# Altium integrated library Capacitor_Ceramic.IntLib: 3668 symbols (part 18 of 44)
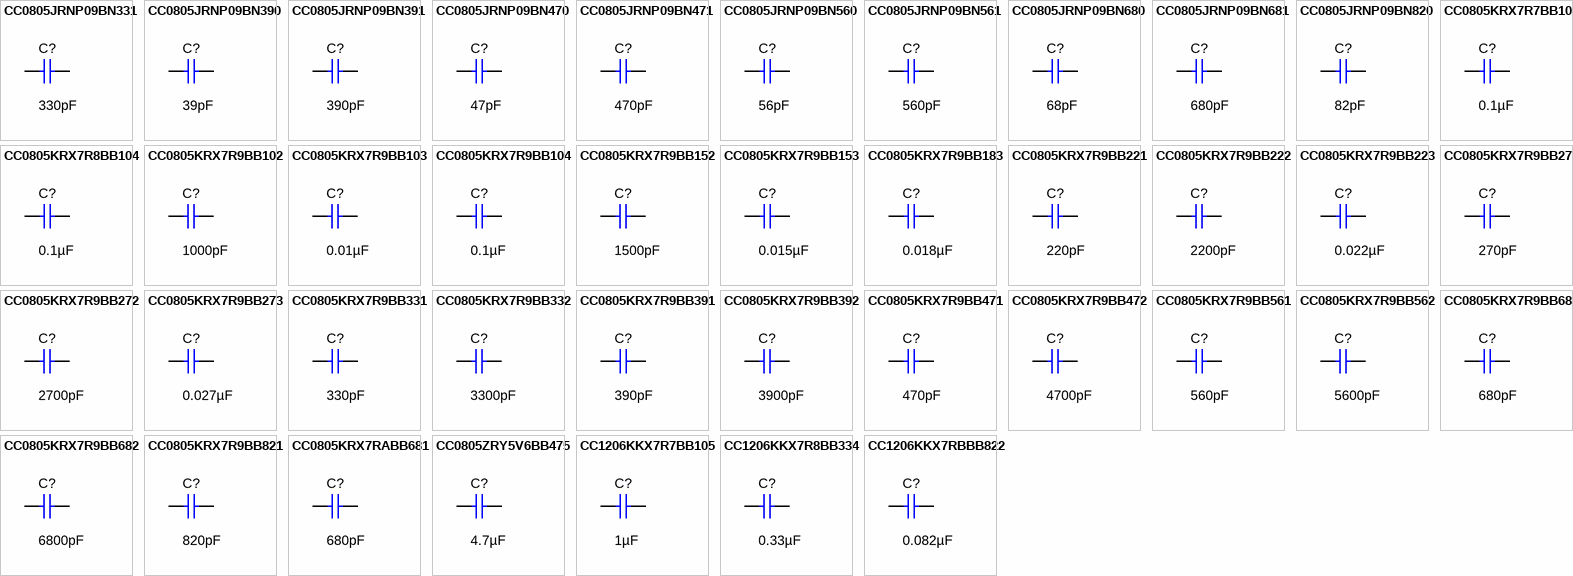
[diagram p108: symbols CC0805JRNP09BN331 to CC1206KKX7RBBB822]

## CC0805JRNP09BN820
designator C?  ValueDisplayed: 82pF  (hidden comment: CC0805JRNP09BN820)
CAP, CERM, 82 pF, 50 V,+/- 5%, C0G/NP0, 0805; Manufacturer: Yageo America; Polarized: N; CompType: Capacitor; Value: 82pF; U/M: EA; Cap_F: 0.000000000082; Tolerance_%: 5; VDC_V: 50; Value2: 50V; TaMin_C: -55; TaMax_C: 125; Cap_Case: 0805; SizeArea_mm2: 2.5; SizeAreaWB_mm2: 6.75; SizeX_mm: 2; SizeY_mm: 1.25; SizeZ_mm: 1.45; AEC Category: Q200
signal-integrity model Cap
simulation model Cap
footprint 0805_HV
footprint 0805_HV1
footprint 0805
footprint 0805M
footprint 0805L
pins: 1, 2

## CC0805KRX7R7BB104
designator C?  ValueDisplayed: 0.1µF  (hidden comment: CC0805KRX7R7BB104)
CAP, CERM, 0.1 µF, 16 V,+/- 10%, X7R, 0805; Manufacturer: Yageo America; Polarized: N; CompType: Capacitor; Value: 0.1uF; U/M: EA; Cap_F: 0.0000001; Tolerance_%: 10; VDC_V: 16; Value2: 16V; TaMin_C: -55; TaMax_C: 125; Cap_Case: 0805; SizeArea_mm2: 2.5; SizeAreaWB_mm2: 6.75; SizeX_mm: 2; SizeY_mm: 1.25; SizeZ_mm: 1.45; AEC Category: Q200; Green_Lifecycle: Active; Green_REACh: Passed
signal-integrity model Cap
simulation model Cap
footprint 0805_HV
footprint 0805_HV1
footprint 0805
footprint 0805M
footprint 0805L
pins: 1, 2

## CC0805KRX7R8BB104
designator C?  ValueDisplayed: 0.1µF  (hidden comment: CC0805KRX7R8BB104)
CAP, CERM, 0.1 µF, 25 V,+/- 10%, X7R, 0805; Manufacturer: Yageo America; Polarized: N; CompType: Capacitor; Value: 0.1uF; U/M: EA; Cap_F: 0.0000001; Tolerance_%: 10; VDC_V: 25; Value2: 25V; TaMin_C: -55; TaMax_C: 125; Cap_Case: 0805; SizeArea_mm2: 2.5; SizeAreaWB_mm2: 6.75; SizeX_mm: 2; SizeY_mm: 1.25; SizeZ_mm: 1.45; AEC Category: Q200; Green_Lifecycle: Active; Green_REACh: Passed
signal-integrity model Cap
simulation model Cap
footprint 0805_HV
footprint 0805_HV1
footprint 0805
footprint 0805M
footprint 0805L
pins: 1, 2

## CC0805KRX7R9BB102
designator C?  ValueDisplayed: 1000pF  (hidden comment: CC0805KRX7R9BB102)
CAP, CERM, 1000 pF, 50 V,+/- 10%, X7R, 0805; Manufacturer: Yageo America; Polarized: N; CompType: Capacitor; Value: 1000pF; U/M: EA; Cap_F: 0.000000001; Tolerance_%: 10; VDC_V: 50; Value2: 50V; TaMin_C: -55; TaMax_C: 125; Cap_Case: 0805; SizeArea_mm2: 2.5; SizeAreaWB_mm2: 6.75; SizeX_mm: 2; SizeY_mm: 1.25; SizeZ_mm: 1.45; AEC Category: Q200
signal-integrity model Cap
simulation model Cap
footprint 0805_HV
footprint 0805_HV1
footprint 0805
footprint 0805M
footprint 0805L
pins: 1, 2

## CC0805KRX7R9BB103
designator C?  ValueDisplayed: 0.01µF  (hidden comment: CC0805KRX7R9BB103)
CAP, CERM, 0.01 µF, 50 V,+/- 10%, X7R, 0805; Manufacturer: Yageo America; Polarized: N; CompType: Capacitor; Value: 0.01uF; U/M: EA; Cap_F: 0.00000001; Tolerance_%: 10; VDC_V: 50; Value2: 50V; TaMin_C: -55; TaMax_C: 125; Cap_Case: 0805; SizeArea_mm2: 2.5; SizeAreaWB_mm2: 6.75; SizeX_mm: 2; SizeY_mm: 1.25; SizeZ_mm: 1.45; AEC Category: Q200; Green_Lifecycle: Active; Green_REACh: Passed
signal-integrity model Cap
simulation model Cap
footprint 0805_HV
footprint 0805_HV1
footprint 0805
footprint 0805M
footprint 0805L
pins: 1, 2

## CC0805KRX7R9BB104
designator C?  ValueDisplayed: 0.1µF  (hidden comment: CC0805KRX7R9BB104)
CAP, CERM, 0.1 µF, 50 V,+/- 10%, X7R, 0805; Manufacturer: Yageo America; Polarized: N; CompType: Capacitor; Value: 0.1uF; U/M: EA; Cap_F: 0.0000001; Tolerance_%: 10; VDC_V: 50; Value2: 50V; TaMin_C: -55; TaMax_C: 125; Cap_Case: 0805; SizeArea_mm2: 2.5; SizeAreaWB_mm2: 6.75; SizeX_mm: 2; SizeY_mm: 1.25; SizeZ_mm: 1.45; AEC Category: Q200; Green_Lifecycle: Active; Green_REACh: Passed
signal-integrity model Cap
simulation model Cap
footprint 0805_HV
footprint 0805_HV1
footprint 0805
footprint 0805M
footprint 0805L
pins: 1, 2

## CC0805KRX7R9BB152
designator C?  ValueDisplayed: 1500pF  (hidden comment: CC0805KRX7R9BB152)
CAP, CERM, 1500 pF, 50 V,+/- 10%, X7R, 0805; Manufacturer: Yageo America; Polarized: N; CompType: Capacitor; Value: 1500pF; U/M: EA; Cap_F: 0.0000000015; Tolerance_%: 10; VDC_V: 50; Value2: 50V; TaMin_C: -55; TaMax_C: 125; Cap_Case: 0805; SizeArea_mm2: 2.5; SizeAreaWB_mm2: 6.75; SizeX_mm: 2; SizeY_mm: 1.25; SizeZ_mm: 1.45; AEC Category: Q200
signal-integrity model Cap
simulation model Cap
footprint 0805_HV
footprint 0805_HV1
footprint 0805
footprint 0805M
footprint 0805L
pins: 1, 2

## CC0805KRX7R9BB153
designator C?  ValueDisplayed: 0.015µF  (hidden comment: CC0805KRX7R9BB153)
CAP, CERM, 0.015 µF, 50 V,+/- 10%, X7R, 0805; Manufacturer: Yageo America; Polarized: N; CompType: Capacitor; Value: 0.015uF; U/M: EA; Cap_F: 0.000000015; Tolerance_%: 10; VDC_V: 50; Value2: 50V; TaMin_C: -55; TaMax_C: 125; Cap_Case: 0805; SizeArea_mm2: 2.5; SizeAreaWB_mm2: 6.75; SizeX_mm: 2; SizeY_mm: 1.25; SizeZ_mm: 1.45; AEC Category: Q200
signal-integrity model Cap
simulation model Cap
footprint 0805_HV
footprint 0805_HV1
footprint 0805
footprint 0805M
footprint 0805L
pins: 1, 2

## CC0805KRX7R9BB183
designator C?  ValueDisplayed: 0.018µF  (hidden comment: CC0805KRX7R9BB183)
CAP, CERM, 0.018 µF, 50 V,+/- 10%, X7R, 0805; Manufacturer: Yageo America; Polarized: N; CompType: Capacitor; Value: 0.018uF; U/M: EA; Cap_F: 0.000000018; Tolerance_%: 10; VDC_V: 50; Value2: 50V; TaMin_C: -55; TaMax_C: 125; Cap_Case: 0805; SizeArea_mm2: 2.5; SizeAreaWB_mm2: 6.75; SizeX_mm: 2; SizeY_mm: 1.25; SizeZ_mm: 1.45; AEC Category: Q200
signal-integrity model Cap
simulation model Cap
footprint 0805_HV
footprint 0805_HV1
footprint 0805
footprint 0805M
footprint 0805L
pins: 1, 2

## CC0805KRX7R9BB221
designator C?  ValueDisplayed: 220pF  (hidden comment: CC0805KRX7R9BB221)
CAP, CERM, 220 pF, 50 V,+/- 10%, X7R, 0805; Manufacturer: Yageo America; Polarized: N; CompType: Capacitor; Value: 220pF; U/M: EA; Cap_F: 0.00000000022; Tolerance_%: 10; VDC_V: 50; Value2: 50V; TaMin_C: -55; TaMax_C: 125; Cap_Case: 0805; SizeArea_mm2: 2.5; SizeAreaWB_mm2: 6.75; SizeX_mm: 2; SizeY_mm: 1.25; SizeZ_mm: 1.45; AEC Category: Q200
signal-integrity model Cap
simulation model Cap
footprint 0805_HV
footprint 0805_HV1
footprint 0805
footprint 0805M
footprint 0805L
pins: 1, 2

## CC0805KRX7R9BB222
designator C?  ValueDisplayed: 2200pF  (hidden comment: CC0805KRX7R9BB222)
CAP, CERM, 2200 pF, 50 V,+/- 10%, X7R, 0805; Manufacturer: Yageo America; Polarized: N; CompType: Capacitor; Value: 2200pF; U/M: EA; Cap_F: 0.0000000022; Tolerance_%: 10; VDC_V: 50; Value2: 50V; TaMin_C: -55; TaMax_C: 125; Cap_Case: 0805; SizeArea_mm2: 2.5; SizeAreaWB_mm2: 6.75; SizeX_mm: 2; SizeY_mm: 1.25; SizeZ_mm: 1.45; AEC Category: Q200
signal-integrity model Cap
simulation model Cap
footprint 0805_HV
footprint 0805_HV1
footprint 0805
footprint 0805M
footprint 0805L
pins: 1, 2

## CC0805KRX7R9BB223
designator C?  ValueDisplayed: 0.022µF  (hidden comment: CC0805KRX7R9BB223)
CAP, CERM, 0.022 µF, 50 V,+/- 10%, X7R, 0805; Manufacturer: Yageo America; Polarized: N; CompType: Capacitor; Value: 0.022uF; U/M: EA; Cap_F: 0.000000022; Tolerance_%: 10; VDC_V: 50; Value2: 50V; TaMin_C: -55; TaMax_C: 125; Cap_Case: 0805; SizeArea_mm2: 2.5; SizeAreaWB_mm2: 6.75; SizeX_mm: 2; SizeY_mm: 1.25; SizeZ_mm: 1.45; AEC Category: Q200
signal-integrity model Cap
simulation model Cap
footprint 0805_HV
footprint 0805_HV1
footprint 0805
footprint 0805M
footprint 0805L
pins: 1, 2

## CC0805KRX7R9BB271
designator C?  ValueDisplayed: 270pF  (hidden comment: CC0805KRX7R9BB271)
CAP, CERM, 270 pF, 50 V,+/- 10%, X7R, 0805; Manufacturer: Yageo America; Polarized: N; CompType: Capacitor; Value: 270pF; U/M: EA; Cap_F: 0.00000000027; Tolerance_%: 10; VDC_V: 50; Value2: 50V; TaMin_C: -55; TaMax_C: 125; Cap_Case: 0805; SizeArea_mm2: 2.5; SizeAreaWB_mm2: 6.75; SizeX_mm: 2; SizeY_mm: 1.25; SizeZ_mm: 1.45; AEC Category: Q200
signal-integrity model Cap
simulation model Cap
footprint 0805_HV
footprint 0805_HV1
footprint 0805
footprint 0805M
footprint 0805L
pins: 1, 2

## CC0805KRX7R9BB272
designator C?  ValueDisplayed: 2700pF  (hidden comment: CC0805KRX7R9BB272)
CAP, CERM, 2700 pF, 50 V,+/- 10%, X7R, 0805; Manufacturer: Yageo America; Polarized: N; CompType: Capacitor; Value: 2700pF; U/M: EA; Cap_F: 0.0000000027; Tolerance_%: 10; VDC_V: 50; Value2: 50V; TaMin_C: -55; TaMax_C: 125; Cap_Case: 0805; SizeArea_mm2: 2.5; SizeAreaWB_mm2: 6.75; SizeX_mm: 2; SizeY_mm: 1.25; SizeZ_mm: 1.45; AEC Category: Q200
signal-integrity model Cap
simulation model Cap
footprint 0805_HV
footprint 0805_HV1
footprint 0805
footprint 0805M
footprint 0805L
pins: 1, 2

## CC0805KRX7R9BB273
designator C?  ValueDisplayed: 0.027µF  (hidden comment: CC0805KRX7R9BB273)
CAP, CERM, 0.027 µF, 50 V,+/- 10%, X7R, 0805; Manufacturer: Yageo America; Polarized: N; CompType: Capacitor; Value: 0.027uF; U/M: EA; Cap_F: 0.000000027; Tolerance_%: 10; VDC_V: 50; Value2: 50V; TaMin_C: -55; TaMax_C: 125; Cap_Case: 0805; SizeArea_mm2: 2.5; SizeAreaWB_mm2: 6.75; SizeX_mm: 2; SizeY_mm: 1.25; SizeZ_mm: 1.45; AEC Category: Q200
signal-integrity model Cap
simulation model Cap
footprint 0805_HV
footprint 0805_HV1
footprint 0805
footprint 0805M
footprint 0805L
pins: 1, 2

## CC0805KRX7R9BB331
designator C?  ValueDisplayed: 330pF  (hidden comment: CC0805KRX7R9BB331)
CAP, CERM, 330 pF, 50 V,+/- 10%, X7R, 0805; Manufacturer: Yageo America; Polarized: N; CompType: Capacitor; Value: 330pF; U/M: EA; Cap_F: 0.00000000033; Tolerance_%: 10; VDC_V: 50; Value2: 50V; TaMin_C: -55; TaMax_C: 125; Cap_Case: 0805; SizeArea_mm2: 2.5; SizeAreaWB_mm2: 6.75; SizeX_mm: 2; SizeY_mm: 1.25; SizeZ_mm: 1.45; AEC Category: Q200
signal-integrity model Cap
simulation model Cap
footprint 0805_HV
footprint 0805_HV1
footprint 0805
footprint 0805M
footprint 0805L
pins: 1, 2

## CC0805KRX7R9BB332
designator C?  ValueDisplayed: 3300pF  (hidden comment: CC0805KRX7R9BB332)
CAP, CERM, 3300 pF, 50 V,+/- 10%, X7R, 0805; Manufacturer: Yageo America; Polarized: N; CompType: Capacitor; Value: 3300pF; U/M: EA; Cap_F: 0.0000000033; Tolerance_%: 10; VDC_V: 50; Value2: 50V; TaMin_C: -55; TaMax_C: 125; Cap_Case: 0805; SizeArea_mm2: 2.5; SizeAreaWB_mm2: 6.75; SizeX_mm: 2; SizeY_mm: 1.25; SizeZ_mm: 1.45; AEC Category: Q200
signal-integrity model Cap
simulation model Cap
footprint 0805_HV
footprint 0805_HV1
footprint 0805
footprint 0805M
footprint 0805L
pins: 1, 2

## CC0805KRX7R9BB391
designator C?  ValueDisplayed: 390pF  (hidden comment: CC0805KRX7R9BB391)
CAP, CERM, 390 pF, 50 V,+/- 10%, X7R, 0805; Manufacturer: Yageo America; Polarized: N; CompType: Capacitor; Value: 390pF; U/M: EA; Cap_F: 0.00000000039; Tolerance_%: 10; VDC_V: 50; Value2: 50V; TaMin_C: -55; TaMax_C: 125; Cap_Case: 0805; SizeArea_mm2: 2.5; SizeAreaWB_mm2: 6.75; SizeX_mm: 2; SizeY_mm: 1.25; SizeZ_mm: 1.45; AEC Category: Q200
signal-integrity model Cap
simulation model Cap
footprint 0805_HV
footprint 0805_HV1
footprint 0805
footprint 0805M
footprint 0805L
pins: 1, 2

## CC0805KRX7R9BB392
designator C?  ValueDisplayed: 3900pF  (hidden comment: CC0805KRX7R9BB392)
CAP, CERM, 3900 pF, 50 V,+/- 10%, X7R, 0805; Manufacturer: Yageo America; Polarized: N; CompType: Capacitor; Value: 3900pF; U/M: EA; Cap_F: 0.0000000039; Tolerance_%: 10; VDC_V: 50; Value2: 50V; TaMin_C: -55; TaMax_C: 125; Cap_Case: 0805; SizeArea_mm2: 2.5; SizeAreaWB_mm2: 6.75; SizeX_mm: 2; SizeY_mm: 1.25; SizeZ_mm: 1.45; AEC Category: Q200
signal-integrity model Cap
simulation model Cap
footprint 0805_HV
footprint 0805_HV1
footprint 0805
footprint 0805M
footprint 0805L
pins: 1, 2

## CC0805KRX7R9BB471
designator C?  ValueDisplayed: 470pF  (hidden comment: CC0805KRX7R9BB471)
CAP, CERM, 470 pF, 50 V,+/- 10%, X7R, 0805; Manufacturer: Yageo America; Polarized: N; CompType: Capacitor; Value: 470pF; U/M: EA; Cap_F: 0.00000000047; Tolerance_%: 10; VDC_V: 50; Value2: 50V; TaMin_C: -55; TaMax_C: 125; Cap_Case: 0805; SizeArea_mm2: 2.5; SizeAreaWB_mm2: 6.75; SizeX_mm: 2; SizeY_mm: 1.25; SizeZ_mm: 1.45; AEC Category: Q200; Green_Lifecycle: Active; Green_REACh: Passed
signal-integrity model Cap
simulation model Cap
footprint 0805_HV
footprint 0805_HV1
footprint 0805
footprint 0805M
footprint 0805L
pins: 1, 2

## CC0805KRX7R9BB472
designator C?  ValueDisplayed: 4700pF  (hidden comment: CC0805KRX7R9BB472)
CAP, CERM, 4700 pF, 50 V,+/- 10%, X7R, 0805; Manufacturer: Yageo America; Polarized: N; CompType: Capacitor; Value: 4700pF; U/M: EA; Cap_F: 0.0000000047; Tolerance_%: 10; VDC_V: 50; Value2: 50V; TaMin_C: -55; TaMax_C: 125; Cap_Case: 0805; SizeArea_mm2: 2.5; SizeAreaWB_mm2: 6.75; SizeX_mm: 2; SizeY_mm: 1.25; SizeZ_mm: 1.45; AEC Category: Q200
signal-integrity model Cap
simulation model Cap
footprint 0805_HV
footprint 0805_HV1
footprint 0805
footprint 0805M
footprint 0805L
pins: 1, 2

## CC0805KRX7R9BB561
designator C?  ValueDisplayed: 560pF  (hidden comment: CC0805KRX7R9BB561)
CAP, CERM, 560 pF, 50 V,+/- 10%, X7R, 0805; Manufacturer: Yageo America; Polarized: N; CompType: Capacitor; Value: 560pF; U/M: EA; Cap_F: 0.00000000056; Tolerance_%: 10; VDC_V: 50; Value2: 50V; TaMin_C: -55; TaMax_C: 125; Cap_Case: 0805; SizeArea_mm2: 2.5; SizeAreaWB_mm2: 6.75; SizeX_mm: 2; SizeY_mm: 1.25; SizeZ_mm: 1.45; AEC Category: Q200
signal-integrity model Cap
simulation model Cap
footprint 0805_HV
footprint 0805_HV1
footprint 0805
footprint 0805M
footprint 0805L
pins: 1, 2

## CC0805KRX7R9BB562
designator C?  ValueDisplayed: 5600pF  (hidden comment: CC0805KRX7R9BB562)
CAP, CERM, 5600 pF, 50 V,+/- 10%, X7R, 0805; Manufacturer: Yageo America; Polarized: N; CompType: Capacitor; Value: 5600pF; U/M: EA; Cap_F: 0.0000000056; Tolerance_%: 10; VDC_V: 50; Value2: 50V; TaMin_C: -55; TaMax_C: 125; Cap_Case: 0805; SizeArea_mm2: 2.5; SizeAreaWB_mm2: 6.75; SizeX_mm: 2; SizeY_mm: 1.25; SizeZ_mm: 1.45; AEC Category: Q200
signal-integrity model Cap
simulation model Cap
footprint 0805_HV
footprint 0805_HV1
footprint 0805
footprint 0805M
footprint 0805L
pins: 1, 2

## CC0805KRX7R9BB681
designator C?  ValueDisplayed: 680pF  (hidden comment: CC0805KRX7R9BB681)
CAP, CERM, 680 pF, 50 V,+/- 10%, X7R, 0805; Manufacturer: Yageo America; Polarized: N; CompType: Capacitor; Value: 680pF; U/M: EA; Cap_F: 0.00000000068; Tolerance_%: 10; VDC_V: 50; Value2: 50V; TaMin_C: -55; TaMax_C: 125; Cap_Case: 0805; SizeArea_mm2: 2.5; SizeAreaWB_mm2: 6.75; SizeX_mm: 2; SizeY_mm: 1.25; SizeZ_mm: 1.45; AEC Category: Q200
signal-integrity model Cap
simulation model Cap
footprint 0805_HV
footprint 0805_HV1
footprint 0805
footprint 0805M
footprint 0805L
pins: 1, 2

## CC0805KRX7R9BB682
designator C?  ValueDisplayed: 6800pF  (hidden comment: CC0805KRX7R9BB682)
CAP, CERM, 6800 pF, 50 V,+/- 10%, X7R, 0805; Manufacturer: Yageo America; Polarized: N; CompType: Capacitor; Value: 6800pF; U/M: EA; Cap_F: 0.0000000068; Tolerance_%: 10; VDC_V: 50; Value2: 50V; TaMin_C: -55; TaMax_C: 125; Cap_Case: 0805; SizeArea_mm2: 2.5; SizeAreaWB_mm2: 6.75; SizeX_mm: 2; SizeY_mm: 1.25; SizeZ_mm: 1.45; AEC Category: Q200
signal-integrity model Cap
simulation model Cap
footprint 0805_HV
footprint 0805_HV1
footprint 0805
footprint 0805M
footprint 0805L
pins: 1, 2

## CC0805KRX7R9BB821
designator C?  ValueDisplayed: 820pF  (hidden comment: CC0805KRX7R9BB821)
CAP, CERM, 820 pF, 50 V,+/- 10%, X7R, 0805; Manufacturer: Yageo America; Polarized: N; CompType: Capacitor; Value: 820pF; U/M: EA; Cap_F: 0.00000000082; Tolerance_%: 10; VDC_V: 50; Value2: 50V; TaMin_C: -55; TaMax_C: 125; Cap_Case: 0805; SizeArea_mm2: 2.5; SizeAreaWB_mm2: 6.75; SizeX_mm: 2; SizeY_mm: 1.25; SizeZ_mm: 1.45; AEC Category: Q200
signal-integrity model Cap
simulation model Cap
footprint 0805_HV
footprint 0805_HV1
footprint 0805
footprint 0805M
footprint 0805L
pins: 1, 2

## CC0805KRX7RABB681
designator C?  ValueDisplayed: 680pF  (hidden comment: CC0805KRX7RABB681)
CAP, CERM, 680 pF, 200 V,+/- 10%, X7R, 0805; Manufacturer: Yageo America; Polarized: N; CompType: Capacitor; Value: 680pF; U/M: EA; Cap_F: 0.00000000068; Tolerance_%: 10; VDC_V: 200; Value2: 200V; TaMin_C: -55; TaMax_C: 125; Cap_Case: 0805; SizeArea_mm2: 2.5; SizeAreaWB_mm2: 6.75; SizeX_mm: 2; SizeY_mm: 1.25; SizeZ_mm: 1.45; AEC Category: Q200; Green_Lifecycle: Active; Green_REACh: Passed
signal-integrity model Cap
simulation model Cap
footprint 0805_HV
footprint 0805_HV1
footprint 0805
footprint 0805M
footprint 0805L
pins: 1, 2

## CC0805ZRY5V6BB475
designator C?  ValueDisplayed: 4.7µF  (hidden comment: CC0805ZRY5V6BB475)
CAP, CERM, 4.7 µF, 10 V,+80/-20%, Y5V, 0805; Manufacturer: Yageo America; Polarized: N; CompType: Capacitor; Value: 4.7uF; U/M: EA; Cap_F: 0.0000047; Tolerance_%: 80; VDC_V: 10; Value2: 10V; TaMin_C: -30; TaMax_C: 85; Cap_Case: 0805; SizeArea_mm2: 2.5; SizeAreaWB_mm2: 6.75; SizeX_mm: 2; SizeY_mm: 1.25; SizeZ_mm: 1.45; AEC Category: Q200
signal-integrity model Cap
simulation model Cap
footprint 0805_HV
footprint 0805_HV1
footprint 0805
footprint 0805M
footprint 0805L
pins: 1, 2

## CC1206KKX7R7BB105
designator C?  ValueDisplayed: 1µF  (hidden comment: CC1206KKX7R7BB105)
CAP, CERM, 1 µF, 16 V,+/- 10%, X7R, 1206; Manufacturer: Yageo America; Polarized: N; CompType: Capacitor; Value: 1uF; U/M: EA; Cap_F: 0.000001; Tolerance_%: 10; VDC_V: 16; Value2: 16V; TaMin_C: -55; TaMax_C: 125; Cap_Case: 1206; SizeArea_mm2: 5.12; SizeAreaWB_mm2: 10.92; SizeX_mm: 3.2; SizeY_mm: 1.6; SizeZ_mm: 1.35; AEC Category: Q200; Green_Lifecycle: Active; Green_REACh: Passed
signal-integrity model Cap
simulation model Cap
footprint 1206
footprint 1206M
footprint 1206L
pins: 1, 2

## CC1206KKX7R8BB334
designator C?  ValueDisplayed: 0.33µF  (hidden comment: CC1206KKX7R8BB334)
CAP, CERM, 0.33 µF, 25 V,+/- 10%, X7R, 1206; Manufacturer: Yageo America; Polarized: N; CompType: Capacitor; Value: 0.33uF; U/M: EA; Cap_F: 0.00000033; Tolerance_%: 10; VDC_V: 25; Value2: 25V; TaMin_C: -55; TaMax_C: 125; Cap_Case: 1206; SizeArea_mm2: 5.12; SizeAreaWB_mm2: 10.92; SizeX_mm: 3.2; SizeY_mm: 1.6; SizeZ_mm: 1.35; AEC Category: Q200
signal-integrity model Cap
simulation model Cap
footprint 1206
footprint 1206M
footprint 1206L
pins: 1, 2

## CC1206KKX7RBBB822
designator C?  ValueDisplayed: 0.082µF  (hidden comment: CC1206KKX7RBBB822)
CAP, CERM, 0.082 µF, 500 V,+/- 10%, X7R, 1206; Manufacturer: Yageo America; Polarized: N; CompType: Capacitor; Value: 0.082uF; U/M: EA; Cap_F: 0.000000082; Tolerance_%: 10; VDC_V: 500; Value2: 500V; TaMin_C: -55; TaMax_C: 125; Cap_Case: 1206; SizeArea_mm2: 5.12; SizeAreaWB_mm2: 10.92; SizeX_mm: 3.2; SizeY_mm: 1.6; SizeZ_mm: 1.35; AEC Category: Q200
signal-integrity model Cap
simulation model Cap
footprint 1206
footprint 1206M
footprint 1206L
pins: 1, 2

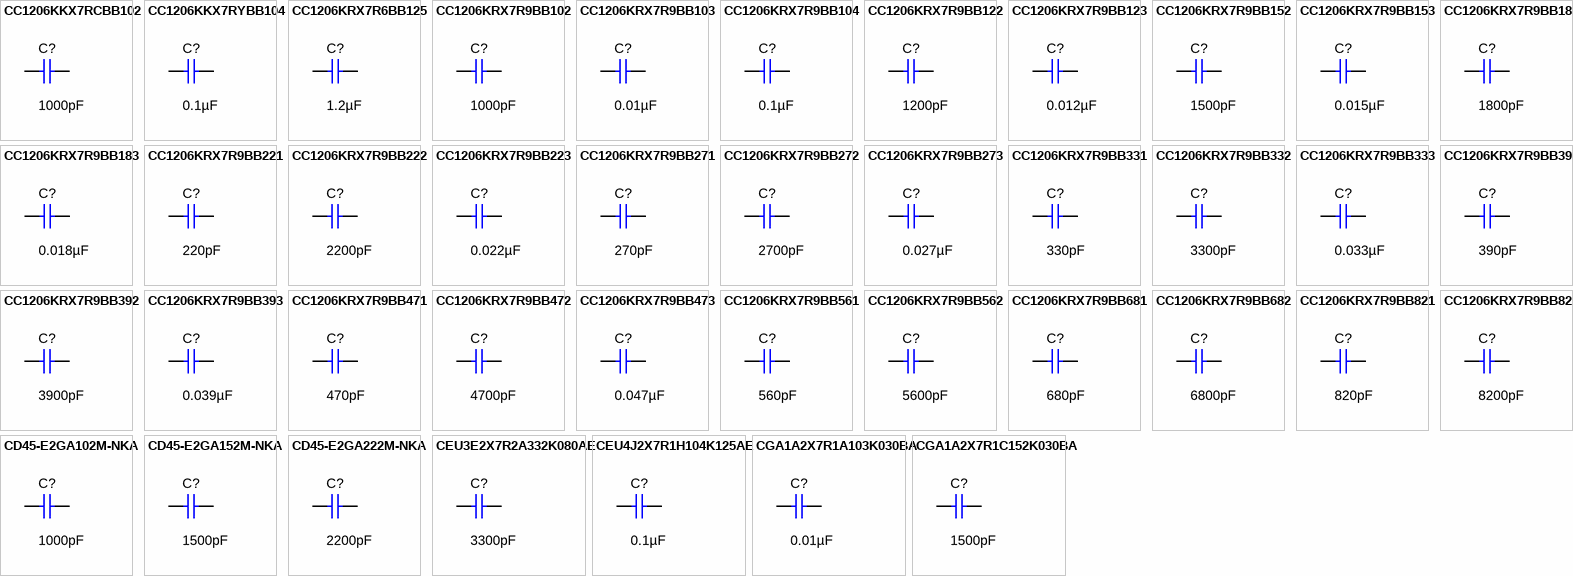
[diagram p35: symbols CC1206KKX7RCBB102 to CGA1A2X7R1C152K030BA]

## CC1206KKX7RCBB102
designator C?  ValueDisplayed: 1000pF  (hidden comment: CC1206KKX7RCBB102)
CAP, CERM, 1000 pF, 1000 V,+/- 10%, X7R, 1206; Manufacturer: Yageo America; Polarized: N; CompType: Capacitor; Value: 1000pF; U/M: EA; Cap_F: 0.000000001; Tolerance_%: 10; VDC_V: 1000; Value2: 1000V; TaMin_C: -55; TaMax_C: 125; Cap_Case: 1206; SizeArea_mm2: 5.12; SizeAreaWB_mm2: 10.92; SizeX_mm: 3.2; SizeY_mm: 1.6; SizeZ_mm: 1.35; AEC Category: Q200; Green_Lifecycle: Active; Green_REACh: Passed
signal-integrity model Cap
simulation model Cap
footprint 1206
footprint 1206M
footprint 1206L
pins: 1, 2

## CC1206KKX7RYBB104
designator C?  ValueDisplayed: 0.1µF  (hidden comment: CC1206KKX7RYBB104)
CAP, CERM, 0.1 µF, 250 V,+/- 10%, X7R, 1206; Manufacturer: Yageo America; Polarized: N; CompType: Capacitor; Value: 0.1uF; U/M: EA; Cap_F: 0.0000001; Tolerance_%: 10; VDC_V: 250; Value2: 250V; TaMin_C: -55; TaMax_C: 125; Cap_Case: 1206; SizeArea_mm2: 5.12; SizeAreaWB_mm2: 10.92; SizeX_mm: 3.2; SizeY_mm: 1.6; SizeZ_mm: 1.35; AEC Category: Q200
signal-integrity model Cap
simulation model Cap
footprint 1206
footprint 1206M
footprint 1206L
pins: 1, 2

## CC1206KRX7R6BB125
designator C?  ValueDisplayed: 1.2µF  (hidden comment: CC1206KRX7R6BB125)
CAP, CERM, 1.2 µF, 10 V,+/- 10%, X7R, 1206; Manufacturer: Yageo America; Polarized: N; CompType: Capacitor; Value: 1.2uF; U/M: EA; Cap_F: 0.0000012; Tolerance_%: 10; Value2: 10V; TaMin_C: -55; TaMax_C: 125; Cap_Case: 1206; SizeArea_mm2: 5.12; SizeAreaWB_mm2: 10.92; SizeX_mm: 3.2; SizeY_mm: 1.6; SizeZ_mm: 1.35; AEC Category: Q200
signal-integrity model Cap
simulation model Cap
footprint 1206
footprint 1206M
footprint 1206L
pins: 1, 2

## CC1206KRX7R9BB102
designator C?  ValueDisplayed: 1000pF  (hidden comment: CC1206KRX7R9BB102)
CAP, CERM, 1000 pF, 50 V,+/- 10%, X7R, 1206; Manufacturer: Yageo America; Polarized: N; CompType: Capacitor; Value: 1000pF; U/M: EA; Cap_F: 0.000000001; Tolerance_%: 10; VDC_V: 50; Value2: 50V; TaMin_C: -55; TaMax_C: 125; Cap_Case: 1206; SizeArea_mm2: 5.12; SizeAreaWB_mm2: 10.92; SizeX_mm: 3.2; SizeY_mm: 1.6; SizeZ_mm: 1.35; AEC Category: Q200
signal-integrity model Cap
simulation model Cap
footprint 1206
footprint 1206M
footprint 1206L
pins: 1, 2

## CC1206KRX7R9BB103
designator C?  ValueDisplayed: 0.01µF  (hidden comment: CC1206KRX7R9BB103)
CAP, CERM, 0.01 µF, 50 V,+/- 10%, X7R, 1206; Manufacturer: Yageo America; Polarized: N; CompType: Capacitor; Value: 0.01uF; U/M: EA; Cap_F: 0.00000001; Tolerance_%: 10; VDC_V: 50; Value2: 50V; TaMin_C: -55; TaMax_C: 125; Cap_Case: 1206; SizeArea_mm2: 5.12; SizeAreaWB_mm2: 10.92; SizeX_mm: 3.2; SizeY_mm: 1.6; SizeZ_mm: 1.35; AEC Category: Q200; Green_Lifecycle: Active; Green_REACh: Passed
signal-integrity model Cap
simulation model Cap
footprint 1206
footprint 1206M
footprint 1206L
pins: 1, 2

## CC1206KRX7R9BB104
designator C?  ValueDisplayed: 0.1µF  (hidden comment: CC1206KRX7R9BB104)
CAP, CERM, 0.1 µF, 50 V,+/- 10%, X7R, 1206; Manufacturer: Yageo America; Polarized: N; CompType: Capacitor; Value: 0.1uF; U/M: EA; Cap_F: 0.0000001; Tolerance_%: 10; VDC_V: 50; Value2: 50V; TaMin_C: -55; TaMax_C: 125; Cap_Case: 1206; SizeArea_mm2: 5.12; SizeAreaWB_mm2: 10.92; SizeX_mm: 3.2; SizeY_mm: 1.6; SizeZ_mm: 1.35; AEC Category: Q200
signal-integrity model Cap
simulation model Cap
footprint 1206
footprint 1206M
footprint 1206L
pins: 1, 2

## CC1206KRX7R9BB122
designator C?  ValueDisplayed: 1200pF  (hidden comment: CC1206KRX7R9BB122)
CAP, CERM, 1200 pF, 50 V,+/- 10%, X7R, 1206; Manufacturer: Yageo America; Polarized: N; CompType: Capacitor; Value: 1200pF; U/M: EA; Cap_F: 0.0000000012; Tolerance_%: 10; VDC_V: 50; Value2: 50V; TaMin_C: -55; TaMax_C: 125; Cap_Case: 1206; SizeArea_mm2: 5.12; SizeAreaWB_mm2: 10.92; SizeX_mm: 3.2; SizeY_mm: 1.6; SizeZ_mm: 1.35; AEC Category: Q200
signal-integrity model Cap
simulation model Cap
footprint 1206
footprint 1206M
footprint 1206L
pins: 1, 2

## CC1206KRX7R9BB123
designator C?  ValueDisplayed: 0.012µF  (hidden comment: CC1206KRX7R9BB123)
CAP, CERM, 0.012 µF, 50 V,+/- 10%, X7R, 1206; Manufacturer: Yageo America; Polarized: N; CompType: Capacitor; Value: 0.012uF; U/M: EA; Cap_F: 0.000000012; Tolerance_%: 10; VDC_V: 50; Value2: 50V; TaMin_C: -55; TaMax_C: 125; Cap_Case: 1206; SizeArea_mm2: 5.12; SizeAreaWB_mm2: 10.92; SizeX_mm: 3.2; SizeY_mm: 1.6; SizeZ_mm: 1.35; AEC Category: Q200
signal-integrity model Cap
simulation model Cap
footprint 1206
footprint 1206M
footprint 1206L
pins: 1, 2

## CC1206KRX7R9BB152
designator C?  ValueDisplayed: 1500pF  (hidden comment: CC1206KRX7R9BB152)
CAP, CERM, 1500 pF, 50 V,+/- 10%, X7R, 1206; Manufacturer: Yageo America; Polarized: N; CompType: Capacitor; Value: 1500pF; U/M: EA; Cap_F: 0.0000000015; Tolerance_%: 10; VDC_V: 50; Value2: 50V; TaMin_C: -55; TaMax_C: 125; Cap_Case: 1206; SizeArea_mm2: 5.12; SizeAreaWB_mm2: 10.92; SizeX_mm: 3.2; SizeY_mm: 1.6; SizeZ_mm: 1.35; AEC Category: Q200
signal-integrity model Cap
simulation model Cap
footprint 1206
footprint 1206M
footprint 1206L
pins: 1, 2

## CC1206KRX7R9BB153
designator C?  ValueDisplayed: 0.015µF  (hidden comment: CC1206KRX7R9BB153)
CAP, CERM, 0.015 µF, 50 V,+/- 10%, X7R, 1206; Manufacturer: Yageo America; Polarized: N; CompType: Capacitor; Value: 0.015uF; U/M: EA; Cap_F: 0.000000015; Tolerance_%: 10; VDC_V: 50; Value2: 50V; TaMin_C: -55; TaMax_C: 125; Cap_Case: 1206; SizeArea_mm2: 5.12; SizeAreaWB_mm2: 10.92; SizeX_mm: 3.2; SizeY_mm: 1.6; SizeZ_mm: 1.35; AEC Category: Q200
signal-integrity model Cap
simulation model Cap
footprint 1206
footprint 1206M
footprint 1206L
pins: 1, 2

## CC1206KRX7R9BB182
designator C?  ValueDisplayed: 1800pF  (hidden comment: CC1206KRX7R9BB182)
CAP, CERM, 1800 pF, 50 V,+/- 10%, X7R, 1206; Manufacturer: Yageo America; Polarized: N; CompType: Capacitor; Value: 1800pF; U/M: EA; Cap_F: 0.0000000018; Tolerance_%: 10; VDC_V: 50; Value2: 50V; TaMin_C: -55; TaMax_C: 125; Cap_Case: 1206; SizeArea_mm2: 5.12; SizeAreaWB_mm2: 10.92; SizeX_mm: 3.2; SizeY_mm: 1.6; SizeZ_mm: 1.35; AEC Category: Q200
signal-integrity model Cap
simulation model Cap
footprint 1206
footprint 1206M
footprint 1206L
pins: 1, 2

## CC1206KRX7R9BB183
designator C?  ValueDisplayed: 0.018µF  (hidden comment: CC1206KRX7R9BB183)
CAP, CERM, 0.018 µF, 50 V,+/- 10%, X7R, 1206; Manufacturer: Yageo America; Polarized: N; CompType: Capacitor; Value: 0.018uF; U/M: EA; Cap_F: 0.000000018; Tolerance_%: 10; VDC_V: 50; Value2: 50V; TaMin_C: -55; TaMax_C: 125; Cap_Case: 1206; SizeArea_mm2: 5.12; SizeAreaWB_mm2: 10.92; SizeX_mm: 3.2; SizeY_mm: 1.6; SizeZ_mm: 1.35; AEC Category: Q200
signal-integrity model Cap
simulation model Cap
footprint 1206
footprint 1206M
footprint 1206L
pins: 1, 2

## CC1206KRX7R9BB221
designator C?  ValueDisplayed: 220pF  (hidden comment: CC1206KRX7R9BB221)
CAP, CERM, 220 pF, 50 V,+/- 10%, X7R, 1206; Manufacturer: Yageo America; Polarized: N; CompType: Capacitor; Value: 220pF; U/M: EA; Cap_F: 0.00000000022; Tolerance_%: 10; VDC_V: 50; Value2: 50V; TaMin_C: -55; TaMax_C: 125; Cap_Case: 1206; SizeArea_mm2: 5.12; SizeAreaWB_mm2: 10.92; SizeX_mm: 3.2; SizeY_mm: 1.6; SizeZ_mm: 1.35; AEC Category: Q200
signal-integrity model Cap
simulation model Cap
footprint 1206
footprint 1206M
footprint 1206L
pins: 1, 2

## CC1206KRX7R9BB222
designator C?  ValueDisplayed: 2200pF  (hidden comment: CC1206KRX7R9BB222)
CAP, CERM, 2200 pF, 50 V,+/- 10%, X7R, 1206; Manufacturer: Yageo America; Polarized: N; CompType: Capacitor; Value: 2200pF; U/M: EA; Cap_F: 0.0000000022; Tolerance_%: 10; VDC_V: 50; Value2: 50V; TaMin_C: -55; TaMax_C: 125; Cap_Case: 1206; SizeArea_mm2: 5.12; SizeAreaWB_mm2: 10.92; SizeX_mm: 3.2; SizeY_mm: 1.6; SizeZ_mm: 1.35; AEC Category: Q200
signal-integrity model Cap
simulation model Cap
footprint 1206
footprint 1206M
footprint 1206L
pins: 1, 2

## CC1206KRX7R9BB223
designator C?  ValueDisplayed: 0.022µF  (hidden comment: CC1206KRX7R9BB223)
CAP, CERM, 0.022 µF, 50 V,+/- 10%, X7R, 1206; Manufacturer: Yageo America; Polarized: N; CompType: Capacitor; Value: 0.022uF; U/M: EA; Cap_F: 0.000000022; Tolerance_%: 10; VDC_V: 50; Value2: 50V; TaMin_C: -55; TaMax_C: 125; Cap_Case: 1206; SizeArea_mm2: 5.12; SizeAreaWB_mm2: 10.92; SizeX_mm: 3.2; SizeY_mm: 1.6; SizeZ_mm: 1.35; AEC Category: Q200
signal-integrity model Cap
simulation model Cap
footprint 1206
footprint 1206M
footprint 1206L
pins: 1, 2

## CC1206KRX7R9BB271
designator C?  ValueDisplayed: 270pF  (hidden comment: CC1206KRX7R9BB271)
CAP, CERM, 270 pF, 50 V,+/- 10%, X7R, 1206; Manufacturer: Yageo America; Polarized: N; CompType: Capacitor; Value: 270pF; U/M: EA; Cap_F: 0.00000000027; Tolerance_%: 10; VDC_V: 50; Value2: 50V; TaMin_C: -55; TaMax_C: 125; Cap_Case: 1206; SizeArea_mm2: 5.12; SizeAreaWB_mm2: 10.92; SizeX_mm: 3.2; SizeY_mm: 1.6; SizeZ_mm: 1.35; AEC Category: Q200
signal-integrity model Cap
simulation model Cap
footprint 1206
footprint 1206M
footprint 1206L
pins: 1, 2

## CC1206KRX7R9BB272
designator C?  ValueDisplayed: 2700pF  (hidden comment: CC1206KRX7R9BB272)
CAP, CERM, 2700 pF, 50 V,+/- 10%, X7R, 1206; Manufacturer: Yageo America; Polarized: N; CompType: Capacitor; Value: 2700pF; U/M: EA; Cap_F: 0.0000000027; Tolerance_%: 10; VDC_V: 50; Value2: 50V; TaMin_C: -55; TaMax_C: 125; Cap_Case: 1206; SizeArea_mm2: 5.12; SizeAreaWB_mm2: 10.92; SizeX_mm: 3.2; SizeY_mm: 1.6; SizeZ_mm: 1.35; AEC Category: Q200
signal-integrity model Cap
simulation model Cap
footprint 1206
footprint 1206M
footprint 1206L
pins: 1, 2

## CC1206KRX7R9BB273
designator C?  ValueDisplayed: 0.027µF  (hidden comment: CC1206KRX7R9BB273)
CAP, CERM, 0.027 µF, 50 V,+/- 10%, X7R, 1206; Manufacturer: Yageo America; Polarized: N; CompType: Capacitor; Value: 0.027uF; U/M: EA; Cap_F: 0.000000027; Tolerance_%: 10; VDC_V: 50; Value2: 50V; TaMin_C: -55; TaMax_C: 125; Cap_Case: 1206; SizeArea_mm2: 5.12; SizeAreaWB_mm2: 10.92; SizeX_mm: 3.2; SizeY_mm: 1.6; SizeZ_mm: 1.35; AEC Category: Q200
signal-integrity model Cap
simulation model Cap
footprint 1206
footprint 1206M
footprint 1206L
pins: 1, 2

## CC1206KRX7R9BB331
designator C?  ValueDisplayed: 330pF  (hidden comment: CC1206KRX7R9BB331)
CAP, CERM, 330 pF, 50 V,+/- 10%, X7R, 1206; Manufacturer: Yageo America; Polarized: N; CompType: Capacitor; Value: 330pF; U/M: EA; Cap_F: 0.00000000033; Tolerance_%: 10; VDC_V: 50; Value2: 50V; TaMin_C: -55; TaMax_C: 125; Cap_Case: 1206; SizeArea_mm2: 5.12; SizeAreaWB_mm2: 10.92; SizeX_mm: 3.2; SizeY_mm: 1.6; SizeZ_mm: 1.35; AEC Category: Q200
signal-integrity model Cap
simulation model Cap
footprint 1206
footprint 1206M
footprint 1206L
pins: 1, 2

## CC1206KRX7R9BB332
designator C?  ValueDisplayed: 3300pF  (hidden comment: CC1206KRX7R9BB332)
CAP, CERM, 3300 pF, 50 V,+/- 10%, X7R, 1206; Manufacturer: Yageo America; Polarized: N; CompType: Capacitor; Value: 3300pF; U/M: EA; Cap_F: 0.0000000033; Tolerance_%: 10; VDC_V: 50; Value2: 50V; TaMin_C: -55; TaMax_C: 125; Cap_Case: 1206; SizeArea_mm2: 5.12; SizeAreaWB_mm2: 10.92; SizeX_mm: 3.2; SizeY_mm: 1.6; SizeZ_mm: 1.35; AEC Category: Q200
signal-integrity model Cap
simulation model Cap
footprint 1206
footprint 1206M
footprint 1206L
pins: 1, 2

## CC1206KRX7R9BB333
designator C?  ValueDisplayed: 0.033µF  (hidden comment: CC1206KRX7R9BB333)
CAP, CERM, 0.033 µF, 50 V,+/- 10%, X7R, 1206; Manufacturer: Yageo America; Polarized: N; CompType: Capacitor; Value: 0.033uF; U/M: EA; Cap_F: 0.000000033; Tolerance_%: 10; VDC_V: 50; Value2: 50V; TaMin_C: -55; TaMax_C: 125; Cap_Case: 1206; SizeArea_mm2: 5.12; SizeAreaWB_mm2: 10.92; SizeX_mm: 3.2; SizeY_mm: 1.6; SizeZ_mm: 1.35; AEC Category: Q200
signal-integrity model Cap
simulation model Cap
footprint 1206
footprint 1206M
footprint 1206L
pins: 1, 2

## CC1206KRX7R9BB391
designator C?  ValueDisplayed: 390pF  (hidden comment: CC1206KRX7R9BB391)
CAP, CERM, 390 pF, 50 V,+/- 10%, X7R, 1206; Manufacturer: Yageo America; Polarized: N; CompType: Capacitor; Value: 390pF; U/M: EA; Cap_F: 0.00000000039; Tolerance_%: 10; VDC_V: 50; Value2: 50V; TaMin_C: -55; TaMax_C: 125; Cap_Case: 1206; SizeArea_mm2: 5.12; SizeAreaWB_mm2: 10.92; SizeX_mm: 3.2; SizeY_mm: 1.6; SizeZ_mm: 1.35; AEC Category: Q200
signal-integrity model Cap
simulation model Cap
footprint 1206
footprint 1206M
footprint 1206L
pins: 1, 2

## CC1206KRX7R9BB392
designator C?  ValueDisplayed: 3900pF  (hidden comment: CC1206KRX7R9BB392)
CAP, CERM, 3900 pF, 50 V,+/- 10%, X7R, 1206; Manufacturer: Yageo America; Polarized: N; CompType: Capacitor; Value: 3900pF; U/M: EA; Cap_F: 0.0000000039; Tolerance_%: 10; VDC_V: 50; Value2: 50V; TaMin_C: -55; TaMax_C: 125; Cap_Case: 1206; SizeArea_mm2: 5.12; SizeAreaWB_mm2: 10.92; SizeX_mm: 3.2; SizeY_mm: 1.6; SizeZ_mm: 1.35; AEC Category: Q200
signal-integrity model Cap
simulation model Cap
footprint 1206
footprint 1206M
footprint 1206L
pins: 1, 2

## CC1206KRX7R9BB393
designator C?  ValueDisplayed: 0.039µF  (hidden comment: CC1206KRX7R9BB393)
CAP, CERM, 0.039 µF, 50 V,+/- 10%, X7R, 1206; Manufacturer: Yageo America; Polarized: N; CompType: Capacitor; Value: 0.039uF; U/M: EA; Cap_F: 0.000000039; Tolerance_%: 10; VDC_V: 50; Value2: 50V; TaMin_C: -55; TaMax_C: 125; Cap_Case: 1206; SizeArea_mm2: 5.12; SizeAreaWB_mm2: 10.92; SizeX_mm: 3.2; SizeY_mm: 1.6; SizeZ_mm: 1.35; AEC Category: Q200
signal-integrity model Cap
simulation model Cap
footprint 1206
footprint 1206M
footprint 1206L
pins: 1, 2

## CC1206KRX7R9BB471
designator C?  ValueDisplayed: 470pF  (hidden comment: CC1206KRX7R9BB471)
CAP, CERM, 470 pF, 50 V,+/- 10%, X7R, 1206; Manufacturer: Yageo America; Polarized: N; CompType: Capacitor; Value: 470pF; U/M: EA; Cap_F: 0.00000000047; Tolerance_%: 10; VDC_V: 50; Value2: 50V; TaMin_C: -55; TaMax_C: 125; Cap_Case: 1206; SizeArea_mm2: 5.12; SizeAreaWB_mm2: 10.92; SizeX_mm: 3.2; SizeY_mm: 1.6; SizeZ_mm: 1.35; AEC Category: Q200
signal-integrity model Cap
simulation model Cap
footprint 1206
footprint 1206M
footprint 1206L
pins: 1, 2

## CC1206KRX7R9BB472
designator C?  ValueDisplayed: 4700pF  (hidden comment: CC1206KRX7R9BB472)
CAP, CERM, 4700 pF, 50 V,+/- 10%, X7R, 1206; Manufacturer: Yageo America; Polarized: N; CompType: Capacitor; Value: 4700pF; U/M: EA; Cap_F: 0.0000000047; Tolerance_%: 10; VDC_V: 50; Value2: 50V; TaMin_C: -55; TaMax_C: 125; Cap_Case: 1206; SizeArea_mm2: 5.12; SizeAreaWB_mm2: 10.92; SizeX_mm: 3.2; SizeY_mm: 1.6; SizeZ_mm: 1.35; AEC Category: Q200
signal-integrity model Cap
simulation model Cap
footprint 1206
footprint 1206M
footprint 1206L
pins: 1, 2

## CC1206KRX7R9BB473
designator C?  ValueDisplayed: 0.047µF  (hidden comment: CC1206KRX7R9BB473)
CAP, CERM, 0.047 µF, 50 V,+/- 10%, X7R, 1206; Manufacturer: Yageo America; Polarized: N; CompType: Capacitor; Value: 0.047uF; U/M: EA; Cap_F: 0.000000047; Tolerance_%: 10; VDC_V: 50; Value2: 50V; TaMin_C: -55; TaMax_C: 125; Cap_Case: 1206; SizeArea_mm2: 5.12; SizeAreaWB_mm2: 10.92; SizeX_mm: 3.2; SizeY_mm: 1.6; SizeZ_mm: 1.35; AEC Category: Q200; Green_Lifecycle: Active; Green_REACh: Passed
signal-integrity model Cap
simulation model Cap
footprint 1206
footprint 1206M
footprint 1206L
pins: 1, 2

## CC1206KRX7R9BB561
designator C?  ValueDisplayed: 560pF  (hidden comment: CC1206KRX7R9BB561)
CAP, CERM, 560 pF, 50 V,+/- 10%, X7R, 1206; Manufacturer: Yageo America; Polarized: N; CompType: Capacitor; Value: 560pF; U/M: EA; Cap_F: 0.00000000056; Tolerance_%: 10; VDC_V: 50; Value2: 50V; TaMin_C: -55; TaMax_C: 125; Cap_Case: 1206; SizeArea_mm2: 5.12; SizeAreaWB_mm2: 10.92; SizeX_mm: 3.2; SizeY_mm: 1.6; SizeZ_mm: 1.35; AEC Category: Q200
signal-integrity model Cap
simulation model Cap
footprint 1206
footprint 1206M
footprint 1206L
pins: 1, 2

## CC1206KRX7R9BB562
designator C?  ValueDisplayed: 5600pF  (hidden comment: CC1206KRX7R9BB562)
CAP, CERM, 5600 pF, 50 V,+/- 10%, X7R, 1206; Manufacturer: Yageo America; Polarized: N; CompType: Capacitor; Value: 5600pF; U/M: EA; Cap_F: 0.0000000056; Tolerance_%: 10; VDC_V: 50; Value2: 50V; TaMin_C: -55; TaMax_C: 125; Cap_Case: 1206; SizeArea_mm2: 5.12; SizeAreaWB_mm2: 10.92; SizeX_mm: 3.2; SizeY_mm: 1.6; SizeZ_mm: 1.35; AEC Category: Q200
signal-integrity model Cap
simulation model Cap
footprint 1206
footprint 1206M
footprint 1206L
pins: 1, 2

## CC1206KRX7R9BB681
designator C?  ValueDisplayed: 680pF  (hidden comment: CC1206KRX7R9BB681)
CAP, CERM, 680 pF, 50 V,+/- 10%, X7R, 1206; Manufacturer: Yageo America; Polarized: N; CompType: Capacitor; Value: 680pF; U/M: EA; Cap_F: 0.00000000068; Tolerance_%: 10; VDC_V: 50; Value2: 50V; TaMin_C: -55; TaMax_C: 125; Cap_Case: 1206; SizeArea_mm2: 5.12; SizeAreaWB_mm2: 10.92; SizeX_mm: 3.2; SizeY_mm: 1.6; SizeZ_mm: 1.35; AEC Category: Q200
signal-integrity model Cap
simulation model Cap
footprint 1206
footprint 1206M
footprint 1206L
pins: 1, 2

## CC1206KRX7R9BB682
designator C?  ValueDisplayed: 6800pF  (hidden comment: CC1206KRX7R9BB682)
CAP, CERM, 6800 pF, 50 V,+/- 10%, X7R, 1206; Manufacturer: Yageo America; Polarized: N; CompType: Capacitor; Value: 6800pF; U/M: EA; Cap_F: 0.0000000068; Tolerance_%: 10; VDC_V: 50; Value2: 50V; TaMin_C: -55; TaMax_C: 125; Cap_Case: 1206; SizeArea_mm2: 5.12; SizeAreaWB_mm2: 10.92; SizeX_mm: 3.2; SizeY_mm: 1.6; SizeZ_mm: 1.35; AEC Category: Q200
signal-integrity model Cap
simulation model Cap
footprint 1206
footprint 1206M
footprint 1206L
pins: 1, 2

## CC1206KRX7R9BB821
designator C?  ValueDisplayed: 820pF  (hidden comment: CC1206KRX7R9BB821)
CAP, CERM, 820 pF, 50 V,+/- 10%, X7R, 1206; Manufacturer: Yageo America; Polarized: N; CompType: Capacitor; Value: 820pF; U/M: EA; Cap_F: 0.00000000082; Tolerance_%: 10; VDC_V: 50; Value2: 50V; TaMin_C: -55; TaMax_C: 125; Cap_Case: 1206; SizeArea_mm2: 5.12; SizeAreaWB_mm2: 10.92; SizeX_mm: 3.2; SizeY_mm: 1.6; SizeZ_mm: 1.35; AEC Category: Q200
signal-integrity model Cap
simulation model Cap
footprint 1206
footprint 1206M
footprint 1206L
pins: 1, 2

## CC1206KRX7R9BB822
designator C?  ValueDisplayed: 8200pF  (hidden comment: CC1206KRX7R9BB822)
CAP, CERM, 8200 pF, 50 V,+/- 10%, X7R, 1206; Manufacturer: Yageo America; Polarized: N; CompType: Capacitor; Value: 8200pF; U/M: EA; Cap_F: 0.0000000082; Tolerance_%: 10; VDC_V: 50; Value2: 50V; TaMin_C: -55; TaMax_C: 125; Cap_Case: 1206; SizeArea_mm2: 5.12; SizeAreaWB_mm2: 10.92; SizeX_mm: 3.2; SizeY_mm: 1.6; SizeZ_mm: 1.35; AEC Category: Q200
signal-integrity model Cap
simulation model Cap
footprint 1206
footprint 1206M
footprint 1206L
pins: 1, 2

## CD45-E2GA102M-NKA
designator C?  ValueDisplayed: 1000pF  (hidden comment: CD45-E2GA102M-NKA)
CAP, CERM, 1000 pF, X1 440 VAC/Y1 400 VAC, +/- 20%, E, D7xT6mm; Manufacturer: TDK; Polarized: N; CompType: Capacitor; Value: 1000pF; U/M: EA; Cap_F: 0.000000001; Tolerance_%: 20; TaMin_C: -25; TaMax_C: 125; Cap_Case: 7x6x11mm; SizeArea_mm2: 63.9; SizeAreaWB_mm2: 101.2; SizeX_mm: 10.65; SizeY_mm: 6; SizeZ_mm: 11; AEC Category: Q200; AC_Safety: X1Y1; VAC_X: 440; VAC_Y: 400
signal-integrity model Cap
simulation model Cap
footprint CD45_700x600x1100
pins: 1, 2

## CD45-E2GA152M-NKA
designator C?  ValueDisplayed: 1500pF  (hidden comment: CD45-E2GA152M-NKA)
CAP, CERM, 1500 pF, X1 440 VAC/Y1 400 VAC, +/- 20%, E, D8xT6mm; Manufacturer: TDK; Polarized: N; CompType: Capacitor; Value: 1500pF; U/M: EA; Cap_F: 0.0000000015; Tolerance_%: 20; TaMin_C: -25; TaMax_C: 125; Cap_Case: 8x6x12mm; SizeArea_mm2: 63.9; SizeAreaWB_mm2: 101.2; SizeX_mm: 10.65; SizeY_mm: 6; SizeZ_mm: 12; AEC Category: Q200; AC_Safety: X1Y1; VAC_X: 440; VAC_Y: 400
signal-integrity model Cap
simulation model Cap
footprint CD45_800x600x1200
pins: 1, 2

## CD45-E2GA222M-NKA
designator C?  ValueDisplayed: 2200pF  (hidden comment: CD45-E2GA222M-NKA)
CAP, CERM, 2200 pF, X1 440 VAC/Y1 400 VAC, +/- 20%, E, D9xT6mm; Manufacturer: TDK; Polarized: N; CompType: Capacitor; Value: 2200pF; U/M: EA; Cap_F: 0.0000000022; Tolerance_%: 20; TaMin_C: -25; TaMax_C: 125; Cap_Case: 9x6x13mm; SizeArea_mm2: 63.9; SizeAreaWB_mm2: 101.2; SizeX_mm: 10.65; SizeY_mm: 6; SizeZ_mm: 13; AEC Category: Q200; Green_Lifecycle: Not Set; Green_REACh: Incomplete; AC_Safety: X1Y1; VAC_X: 440; VAC_Y: 400
signal-integrity model Cap
simulation model Cap
footprint CD45_900x600x1300
pins: 1, 2

## CEU3E2X7R2A332K080AE
designator C?  ValueDisplayed: 3300pF  (hidden comment: CEU3E2X7R2A332K080AE)
CAP, CERM, 3300 pF, 100 V,+/- 10%, X7R, AEC-Q200 Grade 1, 0603; Manufacturer: TDK; Polarized: N; CompType: Capacitor; Value: 3300pF; U/M: EA; Cap_F: 0.0000000033; Tolerance_%: 10; VDC_V: 100; Value2: 100V; TaMin_C: -55; TaMax_C: 125; Cap_Case: 0603; SizeArea_mm2: 1.28; SizeAreaWB_mm2: 4.68; SizeX_mm: 1.6; SizeY_mm: 0.8; SizeZ_mm: 1; AEC Category: Q200; AEC Qualified: Y
signal-integrity model Cap
simulation model Cap
footprint 0603
footprint 0603M
footprint 0603L
footprint 0603_HV
footprint 0603S
pins: 1, 2

## CEU4J2X7R1H104K125AE
designator C?  ValueDisplayed: 0.1µF  (hidden comment: CEU4J2X7R1H104K125AE)
CAP, CERM, 0.1 µF, 50 V,+/- 10%, X7R, AEC-Q200 Grade 1, 0805; Manufacturer: TDK; Polarized: N; CompType: Capacitor; Value: 0.1uF; U/M: EA; Cap_F: 0.0000001; Tolerance_%: 10; VDC_V: 50; Value2: 50V; TaMin_C: -55; TaMax_C: 125; Cap_Case: 0805; SizeArea_mm2: 2.5; SizeAreaWB_mm2: 6.75; SizeX_mm: 2; SizeY_mm: 1.25; SizeZ_mm: 1.5; AEC Category: Q200; AEC Qualified: Y; AEC Grade: 1
signal-integrity model Cap
simulation model Cap
footprint 0805_150
pins: 1, 2

## CGA1A2X7R1A103K030BA
designator C?  ValueDisplayed: 0.01µF  (hidden comment: CGA1A2X7R1A103K030BA)
CAP, CERM, 0.01 µF, 10 V,+/- 10%, X7R, AEC-Q200 Grade 1, 0201; Manufacturer: TDK; Polarized: N; CompType: Capacitor; Value: 0.01uF; U/M: EA; Cap_F: 0.00000001; Tolerance_%: 10; ESR_ohm: 0.280214; Value1: 0.280214 ohm; Value2: 10V; IRMS_A: 0.245718; TaMin_C: -55; TaMax_C: 125; Cap_Case: 0201; SizeArea_mm2: 0.18; SizeAreaWB_mm2: 2.08; SizeX_mm: 0.6; SizeY_mm: 0.3; SizeZ_mm: 0.33; AEC Category: Q200; AEC Qualified: Y; AEC Grade: 1
signal-integrity model Cap
simulation model Cap
footprint 0201_033
footprint 0201_033M
footprint 0201_033L
pins: 1, 2

## CGA1A2X7R1C152K030BA
designator C?  ValueDisplayed: 1500pF  (hidden comment: CGA1A2X7R1C152K030BA)
CAP, CERM, 1500 pF, 16 V,+/- 10%, X7R, 0201; Manufacturer: TDK; Polarized: N; CompType: Capacitor; Value: 1500pF; U/M: EA; Cap_F: 0.0000000015; Tolerance_%: 10; VDC_V: 16; Value2: 16V; TaMin_C: -55; TaMax_C: 125; Cap_Case: 0201; SizeArea_mm2: 0.18; SizeAreaWB_mm2: 2.08; SizeX_mm: 0.6; SizeY_mm: 0.3; SizeZ_mm: 0.26; AEC Category: Q200
signal-integrity model Cap
simulation model Cap
footprint 0201
footprint 0201M
footprint 0201L
footprint 0201_Silk
pins: 1, 2

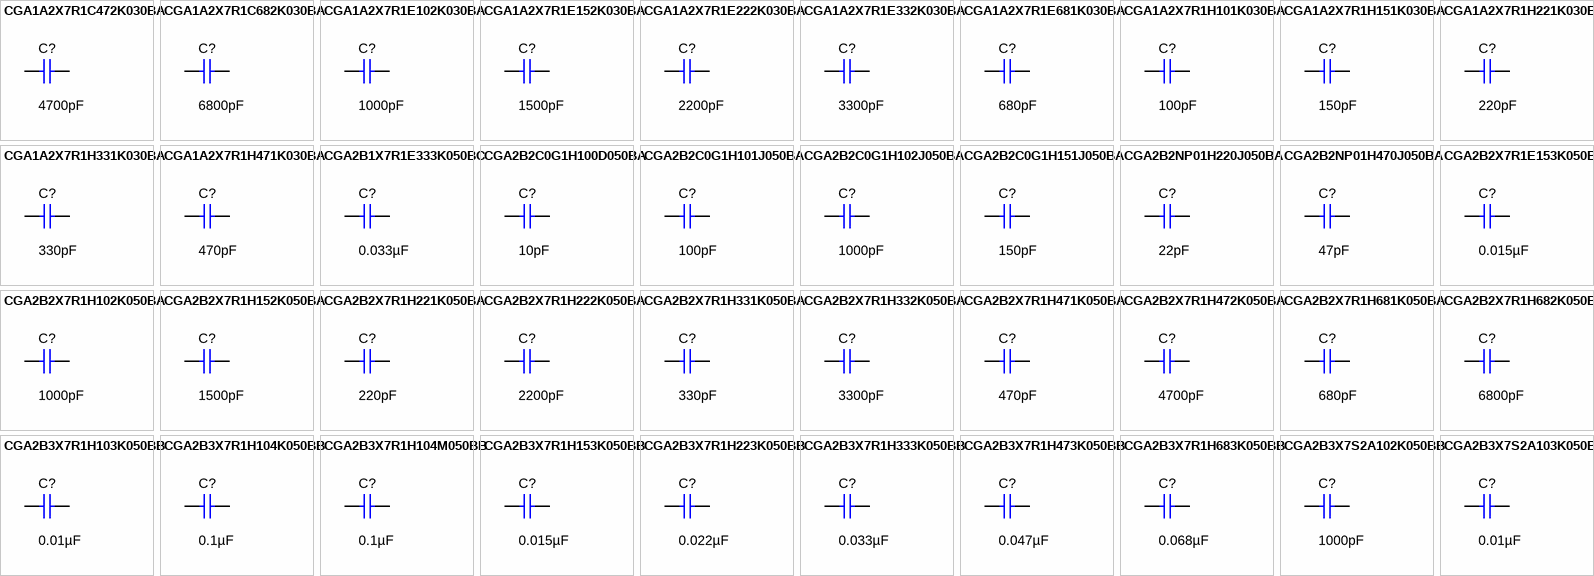
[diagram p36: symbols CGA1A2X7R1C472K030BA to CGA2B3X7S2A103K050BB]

## CGA1A2X7R1C472K030BA
designator C?  ValueDisplayed: 4700pF  (hidden comment: CGA1A2X7R1C472K030BA)
CAP, CERM, 4700 pF, 16 V,+/- 10%, X7R, AEC-Q200 Grade 1, 0201; Manufacturer: TDK; Polarized: N; CompType: Capacitor; Value: 4700pF; U/M: EA; Cap_F: 0.0000000047; Tolerance_%: 10; ESR_ohm: 0.584216; Value1: 0.584216 ohm; VDC_V: 16; Value2: 16V; IRMS_A: 0.218326; TaMin_C: -55; TaMax_C: 125; Cap_Case: 0201; SizeArea_mm2: 0.18; SizeAreaWB_mm2: 2.08; SizeX_mm: 0.6; SizeY_mm: 0.3; SizeZ_mm: 0.33; AEC Category: Q200; AEC Qualified: Y; AEC Grade: 1
signal-integrity model Cap
simulation model Cap
footprint 0201_033
footprint 0201_033M
footprint 0201_033L
pins: 1, 2

## CGA1A2X7R1C682K030BA
designator C?  ValueDisplayed: 6800pF  (hidden comment: CGA1A2X7R1C682K030BA)
CAP, CERM, 6800 pF, 16 V,+/- 10%, X7R, AEC-Q200 Grade 1, 0201; Manufacturer: TDK; Polarized: N; CompType: Capacitor; Value: 6800pF; U/M: EA; Cap_F: 0.0000000068; Tolerance_%: 10; ESR_ohm: 0.498938; Value1: 0.498938 ohm; VDC_V: 16; Value2: 16V; IRMS_A: 0.274308; TaMin_C: -55; TaMax_C: 125; Cap_Case: 0201; SizeArea_mm2: 0.18; SizeAreaWB_mm2: 2.08; SizeX_mm: 0.6; SizeY_mm: 0.3; SizeZ_mm: 0.33; AEC Category: Q200; AEC Qualified: Y; AEC Grade: 1
signal-integrity model Cap
simulation model Cap
footprint 0201_033
footprint 0201_033M
footprint 0201_033L
pins: 1, 2

## CGA1A2X7R1E102K030BA
designator C?  ValueDisplayed: 1000pF  (hidden comment: CGA1A2X7R1E102K030BA)
CAP, CERM, 1000 pF, 25 V,+/- 10%, X7R, AEC-Q200 Grade 1, 0201; Manufacturer: TDK; Polarized: N; CompType: Capacitor; Value: 1000pF; U/M: EA; Cap_F: 0.000000001; Tolerance_%: 10; ESR_ohm: 2.5722; Value1: 2.5722 ohm; VDC_V: 25; Value2: 25V; IRMS_A: 0.143158; TaMin_C: -55; TaMax_C: 125; Cap_Case: 0201; SizeArea_mm2: 0.18; SizeAreaWB_mm2: 2.08; SizeX_mm: 0.6; SizeY_mm: 0.3; SizeZ_mm: 0.33; AEC Category: Q200; AEC Qualified: Y; AEC Grade: 1
signal-integrity model Cap
simulation model Cap
footprint 0201_033
footprint 0201_033M
footprint 0201_033L
pins: 1, 2

## CGA1A2X7R1E152K030BA
designator C?  ValueDisplayed: 1500pF  (hidden comment: CGA1A2X7R1E152K030BA)
CAP, CERM, 1500 pF, 25 V,+/- 10%, X7R, AEC-Q200 Grade 1, 0201; Manufacturer: TDK; Polarized: N; CompType: Capacitor; Value: 1500pF; U/M: EA; Cap_F: 0.0000000015; Tolerance_%: 10; ESR_ohm: 1.59106; Value1: 1.59106 ohm; VDC_V: 25; Value2: 25V; IRMS_A: 0.171024; TaMin_C: -55; TaMax_C: 125; Cap_Case: 0201; SizeArea_mm2: 0.18; SizeAreaWB_mm2: 2.08; SizeX_mm: 0.6; SizeY_mm: 0.3; SizeZ_mm: 0.33; AEC Category: Q200; AEC Qualified: Y; AEC Grade: 1
signal-integrity model Cap
simulation model Cap
footprint 0201_033
footprint 0201_033M
footprint 0201_033L
pins: 1, 2

## CGA1A2X7R1E222K030BA
designator C?  ValueDisplayed: 2200pF  (hidden comment: CGA1A2X7R1E222K030BA)
CAP, CERM, 2200 pF, 25 V,+/- 10%, X7R, AEC-Q200 Grade 1, 0201; Manufacturer: TDK; Polarized: N; CompType: Capacitor; Value: 2200pF; U/M: EA; Cap_F: 0.0000000022; Tolerance_%: 10; ESR_ohm: 1.26834; Value1: 1.26834 ohm; VDC_V: 25; Value2: 25V; IRMS_A: 0.201468; TaMin_C: -55; TaMax_C: 125; Cap_Case: 0201; SizeArea_mm2: 0.18; SizeAreaWB_mm2: 2.08; SizeX_mm: 0.6; SizeY_mm: 0.3; SizeZ_mm: 0.33; AEC Category: Q200; AEC Qualified: Y; AEC Grade: 1
signal-integrity model Cap
simulation model Cap
footprint 0201_033
footprint 0201_033M
footprint 0201_033L
pins: 1, 2

## CGA1A2X7R1E332K030BA
designator C?  ValueDisplayed: 3300pF  (hidden comment: CGA1A2X7R1E332K030BA)
CAP, CERM, 3300 pF, 25 V,+/- 10%, X7R, AEC-Q200 Grade 1, 0201; Manufacturer: TDK; Polarized: N; CompType: Capacitor; Value: 3300pF; U/M: EA; Cap_F: 0.0000000033; Tolerance_%: 10; ESR_ohm: 0.741177; Value1: 0.741177 ohm; VDC_V: 25; Value2: 25V; IRMS_A: 0.270049; TaMin_C: -55; TaMax_C: 125; Cap_Case: 0201; SizeArea_mm2: 0.18; SizeAreaWB_mm2: 2.08; SizeX_mm: 0.6; SizeY_mm: 0.3; SizeZ_mm: 0.33; AEC Category: Q200; AEC Qualified: Y; AEC Grade: 1
signal-integrity model Cap
simulation model Cap
footprint 0201_033
footprint 0201_033M
footprint 0201_033L
pins: 1, 2

## CGA1A2X7R1E681K030BA
designator C?  ValueDisplayed: 680pF  (hidden comment: CGA1A2X7R1E681K030BA)
CAP, CERM, 680 pF, 25 V,+/- 10%, X7R, AEC-Q200 Grade 1, 0201; Manufacturer: TDK; Polarized: N; CompType: Capacitor; Value: 680pF; U/M: EA; Cap_F: 0.00000000068; Tolerance_%: 10; ESR_ohm: 3.57588; Value1: 3.57588 ohm; VDC_V: 25; Value2: 25V; IRMS_A: 0.125404; TaMin_C: -55; TaMax_C: 125; Cap_Case: 0201; SizeArea_mm2: 0.18; SizeAreaWB_mm2: 2.08; SizeX_mm: 0.6; SizeY_mm: 0.3; SizeZ_mm: 0.33; AEC Category: Q200; AEC Qualified: Y; AEC Grade: 1
signal-integrity model Cap
simulation model Cap
footprint 0201_033
footprint 0201_033M
footprint 0201_033L
pins: 1, 2

## CGA1A2X7R1H101K030BA
designator C?  ValueDisplayed: 100pF  (hidden comment: CGA1A2X7R1H101K030BA)
CAP, CERM, 100 pF, 50 V,+/- 10%, X7R, AEC-Q200 Grade 1, 0201; Manufacturer: TDK; Polarized: N; CompType: Capacitor; Value: 100pF; U/M: EA; Cap_F: 0.0000000001; Tolerance_%: 10; ESR_ohm: 23.395; Value1: 23.395 ohm; VDC_V: 50; Value2: 50V; IRMS_A: 0.188082; TaMin_C: -55; TaMax_C: 125; Cap_Case: 0201; SizeArea_mm2: 0.18; SizeAreaWB_mm2: 2.08; SizeX_mm: 0.6; SizeY_mm: 0.3; SizeZ_mm: 0.33; AEC Category: Q200; AEC Qualified: Y; AEC Grade: 1
signal-integrity model Cap
simulation model Cap
footprint 0201_033
footprint 0201_033M
footprint 0201_033L
pins: 1, 2

## CGA1A2X7R1H151K030BA
designator C?  ValueDisplayed: 150pF  (hidden comment: CGA1A2X7R1H151K030BA)
CAP, CERM, 150 pF, 50 V,+/- 10%, X7R, AEC-Q200 Grade 1, 0201; Manufacturer: TDK; Polarized: N; CompType: Capacitor; Value: 150pF; U/M: EA; Cap_F: 0.00000000015; Tolerance_%: 10; ESR_ohm: 17.6682; Value1: 17.6682 ohm; VDC_V: 50; Value2: 50V; IRMS_A: 0.191621; TaMin_C: -55; TaMax_C: 125; Cap_Case: 0201; SizeArea_mm2: 0.18; SizeAreaWB_mm2: 2.08; SizeX_mm: 0.6; SizeY_mm: 0.3; SizeZ_mm: 0.33; AEC Category: Q200; AEC Qualified: Y; AEC Grade: 1
signal-integrity model Cap
simulation model Cap
footprint 0201_033
footprint 0201_033M
footprint 0201_033L
pins: 1, 2

## CGA1A2X7R1H221K030BA
designator C?  ValueDisplayed: 220pF  (hidden comment: CGA1A2X7R1H221K030BA)
CAP, CERM, 220 pF, 50 V,+/- 10%, X7R, AEC-Q200 Grade 1, 0201; Manufacturer: TDK; Polarized: N; CompType: Capacitor; Value: 220pF; U/M: EA; Cap_F: 0.00000000022; Tolerance_%: 10; ESR_ohm: 11.6275; Value1: 11.6275 ohm; VDC_V: 50; Value2: 50V; IRMS_A: 0.200785; TaMin_C: -55; TaMax_C: 125; Cap_Case: 0201; SizeArea_mm2: 0.18; SizeAreaWB_mm2: 2.08; SizeX_mm: 0.6; SizeY_mm: 0.3; SizeZ_mm: 0.33; AEC Category: Q200; AEC Qualified: Y; AEC Grade: 1
signal-integrity model Cap
simulation model Cap
footprint 0201_033
footprint 0201_033M
footprint 0201_033L
pins: 1, 2

## CGA1A2X7R1H331K030BA
designator C?  ValueDisplayed: 330pF  (hidden comment: CGA1A2X7R1H331K030BA)
CAP, CERM, 330 pF, 50 V,+/- 10%, X7R, AEC-Q200 Grade 1, 0201; Manufacturer: TDK; Polarized: N; CompType: Capacitor; Value: 330pF; U/M: EA; Cap_F: 0.00000000033; Tolerance_%: 10; ESR_ohm: 8.05302; Value1: 8.05302 ohm; VDC_V: 50; Value2: 50V; IRMS_A: 0.210618; TaMin_C: -55; TaMax_C: 125; Cap_Case: 0201; SizeArea_mm2: 0.18; SizeAreaWB_mm2: 2.08; SizeX_mm: 0.6; SizeY_mm: 0.3; SizeZ_mm: 0.33; AEC Category: Q200; AEC Qualified: Y; AEC Grade: 1
signal-integrity model Cap
simulation model Cap
footprint 0201_033
footprint 0201_033M
footprint 0201_033L
pins: 1, 2

## CGA1A2X7R1H471K030BA
designator C?  ValueDisplayed: 470pF  (hidden comment: CGA1A2X7R1H471K030BA)
CAP, CERM, 470 pF, 50 V,+/- 10%, X7R, AEC-Q200 Grade 1, 0201; Manufacturer: TDK; Polarized: N; CompType: Capacitor; Value: 470pF; U/M: EA; Cap_F: 0.00000000047; Tolerance_%: 10; ESR_ohm: 5.54785; Value1: 5.54785 ohm; VDC_V: 50; Value2: 50V; IRMS_A: 0.228855; TaMin_C: -55; TaMax_C: 125; Cap_Case: 0201; SizeArea_mm2: 0.18; SizeAreaWB_mm2: 2.08; SizeX_mm: 0.6; SizeY_mm: 0.3; SizeZ_mm: 0.33; AEC Category: Q200; AEC Qualified: Y; AEC Grade: 1
signal-integrity model Cap
simulation model Cap
footprint 0201_033
footprint 0201_033M
footprint 0201_033L
pins: 1, 2

## CGA2B1X7R1E333K050BC
designator C?  ValueDisplayed: 0.033µF  (hidden comment: CGA2B1X7R1E333K050BC)
CAP, CERM, 0.033 µF, 25 V,+/- 10%, X7R, AEC-Q200 Grade 1, 0402; Manufacturer: TDK; Polarized: N; CompType: Capacitor; Value: 0.033uF; U/M: EA; Cap_F: 0.000000033; Tolerance_%: 10; VDC_V: 25; Value2: 25V; TaMin_C: -55; TaMax_C: 125; Cap_Case: 0402; SizeArea_mm2: 0.5; SizeAreaWB_mm2: 3; SizeX_mm: 1; SizeZ_mm: 0.6; AEC Category: Q200; AEC Qualified: Y
signal-integrity model Cap
simulation model Cap
footprint 0402
footprint 0402M
footprint 0402L
footprint 0402S
pins: 1, 2

## CGA2B2C0G1H100D050BA
designator C?  ValueDisplayed: 10pF  (hidden comment: CGA2B2C0G1H100D050BA)
CAP, CERM, 10 pF, 50 V,+/- 5%, C0G/NP0, AEC-Q200 Grade 1, 0402; Manufacturer: TDK; Polarized: N; CompType: Capacitor; Value: 10pF; U/M: EA; Cap_F: 0.00000000001; Tolerance_%: 5; VDC_V: 50; Value2: 50V; TaMin_C: -55; TaMax_C: 125; Cap_Case: 0402; SizeArea_mm2: 0.5; SizeAreaWB_mm2: 3; SizeX_mm: 1; SizeZ_mm: 0.6; AEC Category: Q200; AEC Qualified: Y
signal-integrity model Cap
simulation model Cap
footprint 0402
footprint 0402M
footprint 0402L
footprint 0402S
pins: 1, 2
